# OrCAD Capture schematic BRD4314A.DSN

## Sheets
1 05: Debugger: size A3; title: BGM220P Explorer Kit; rev: A01; company: Silicon Labs; note: BRD4314A; note: MAH; note: RGU
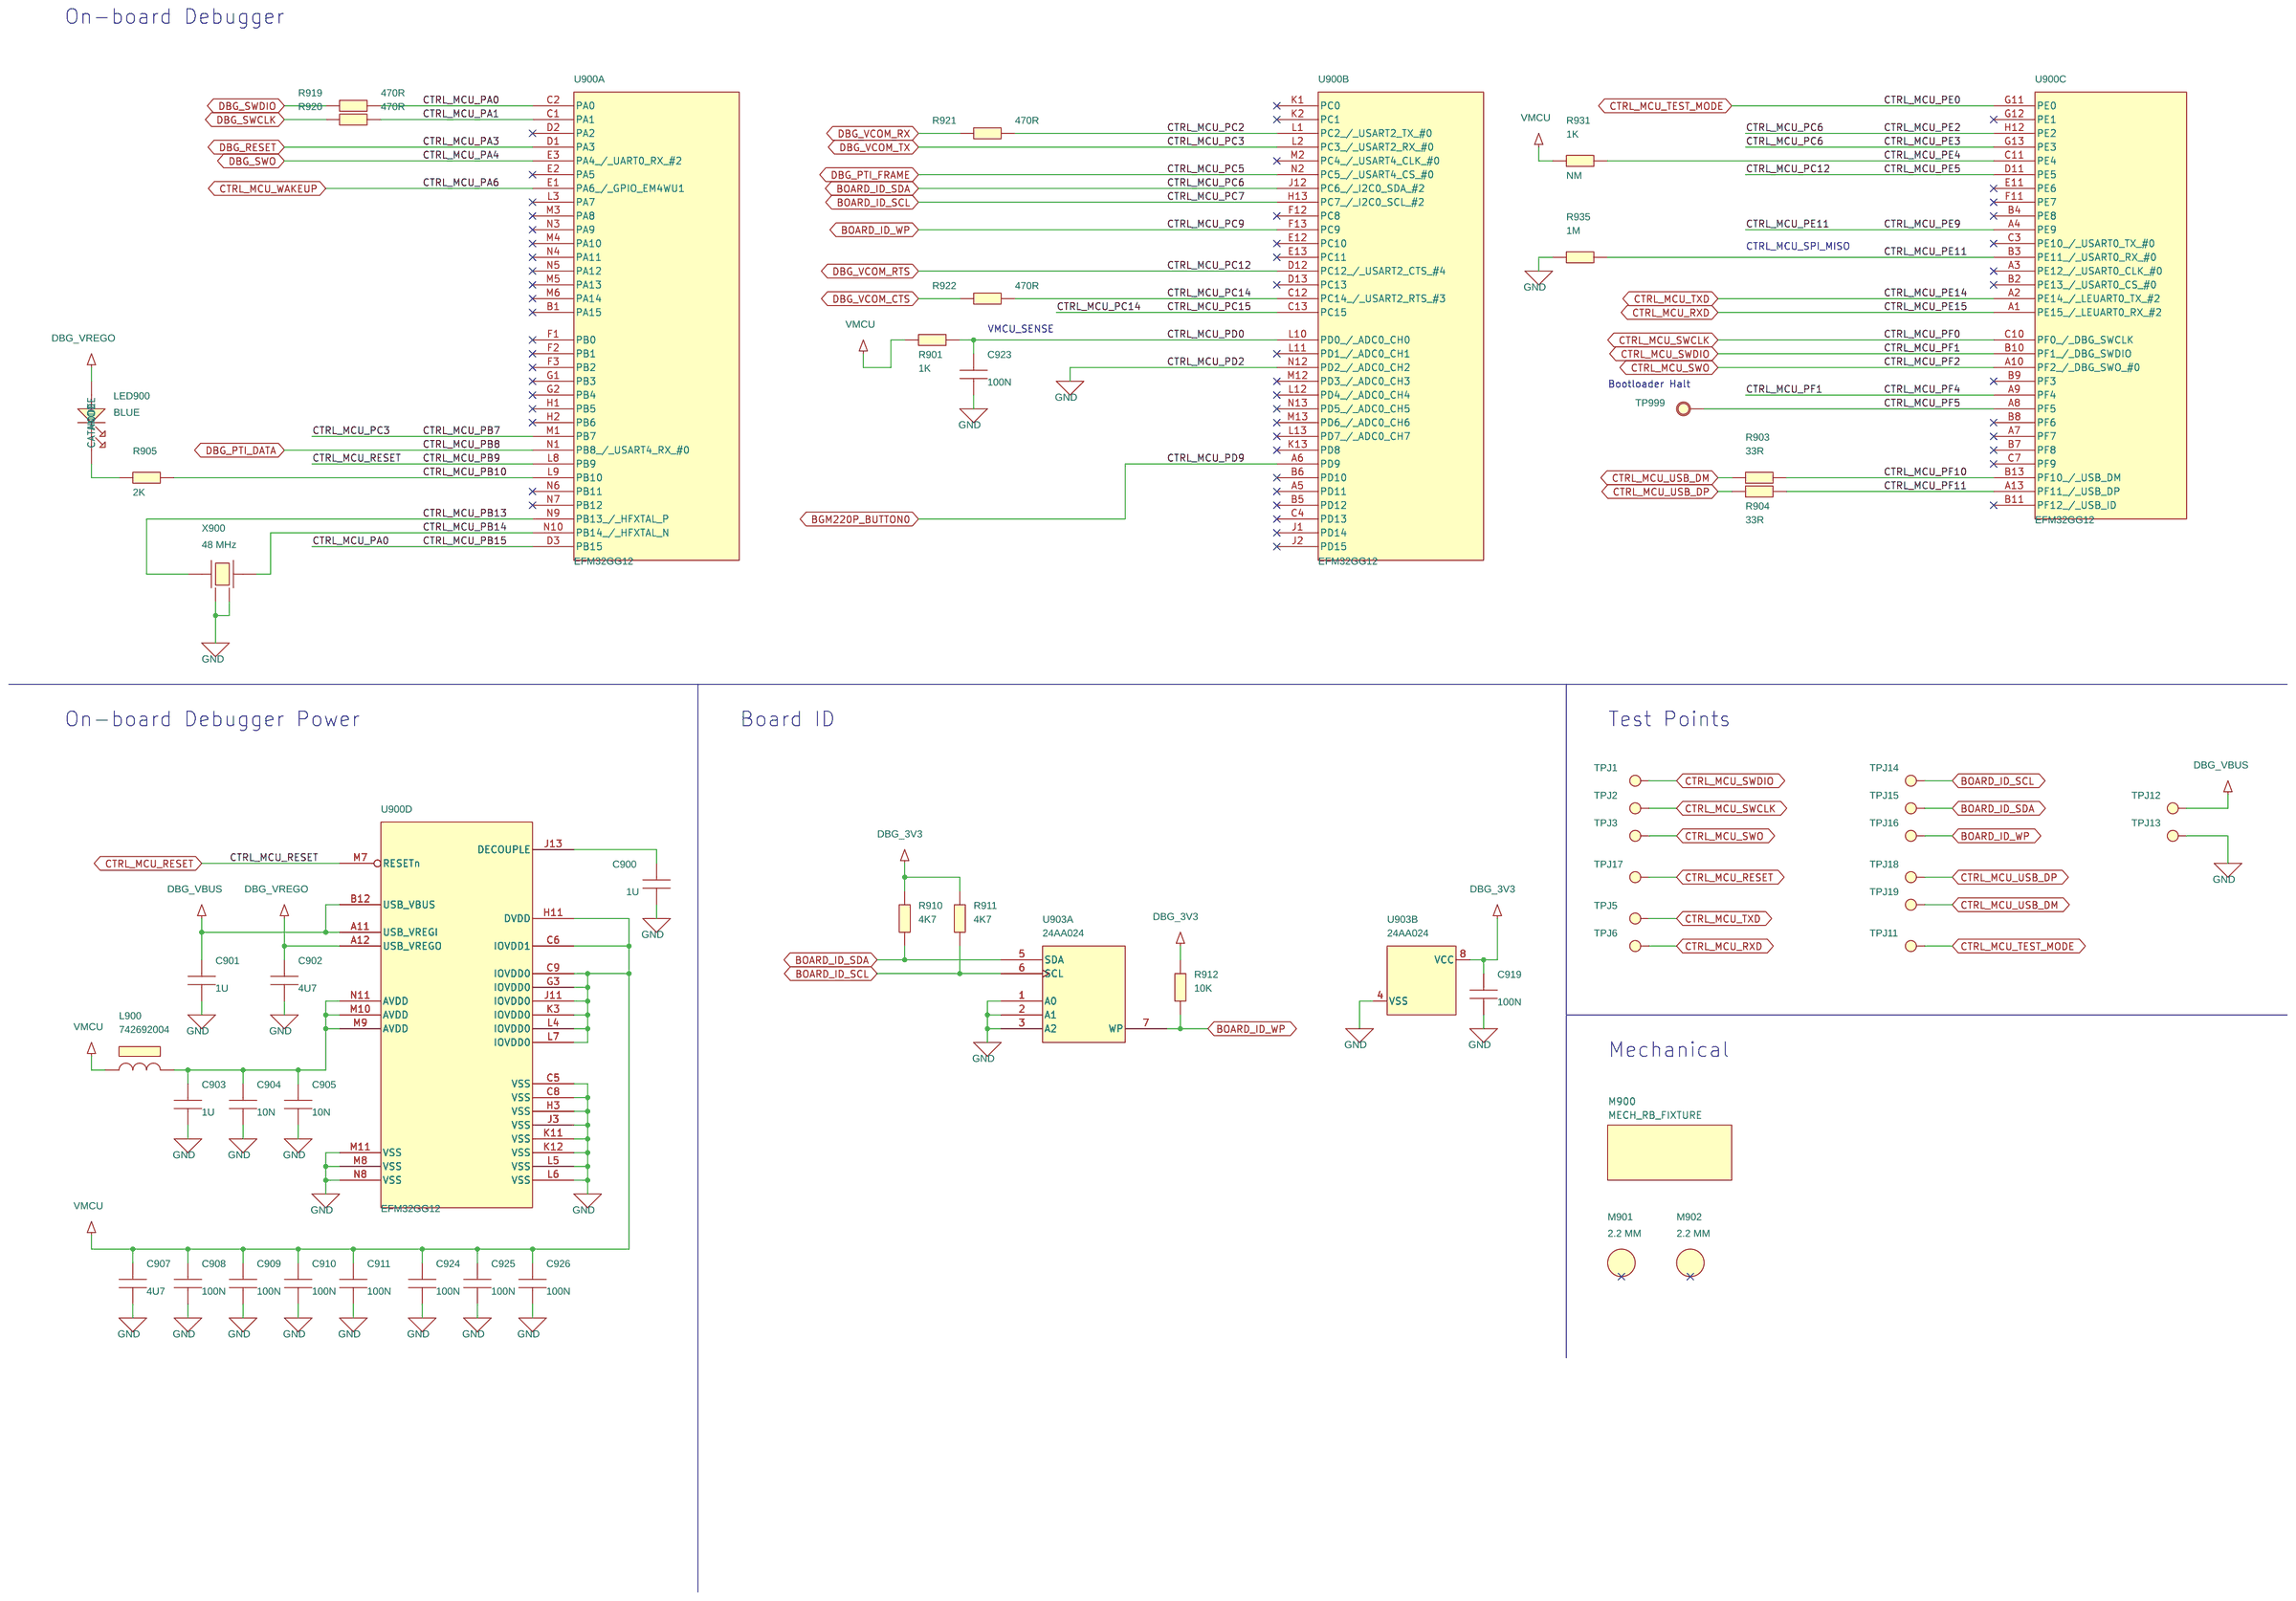
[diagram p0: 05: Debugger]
2 02: BGM220P: size A3
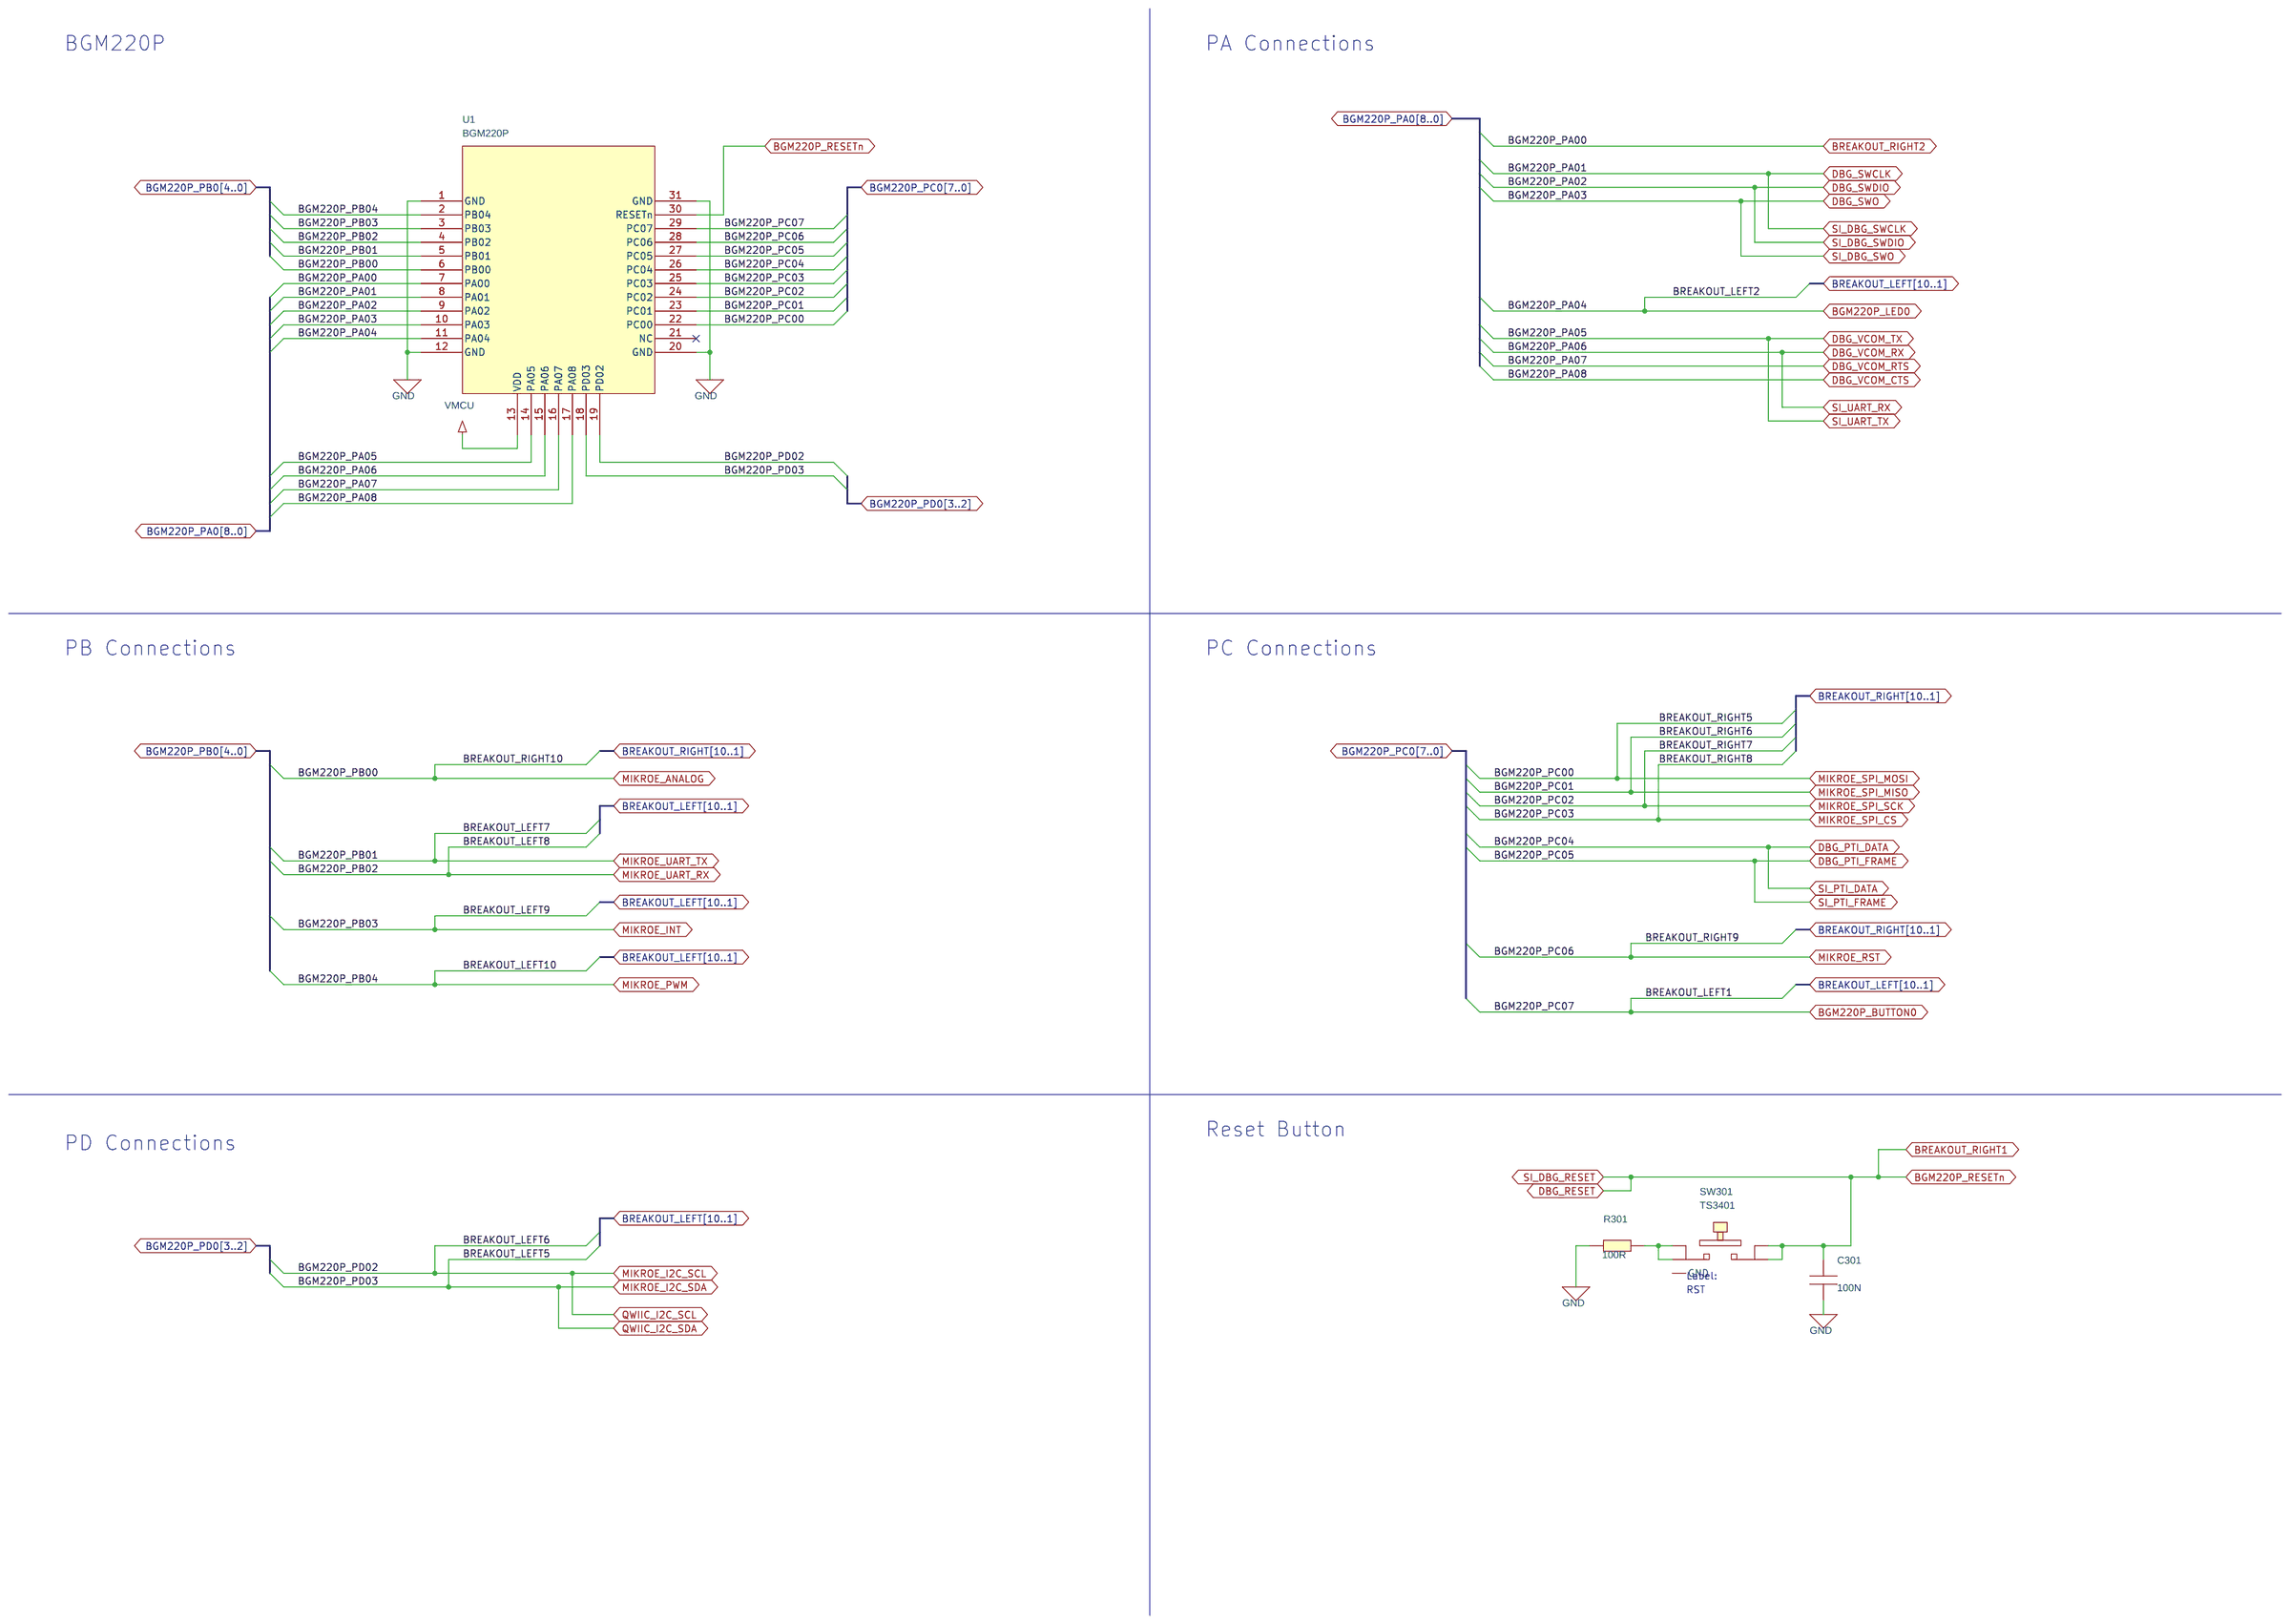
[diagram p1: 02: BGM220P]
3 04: Board Power: size A3
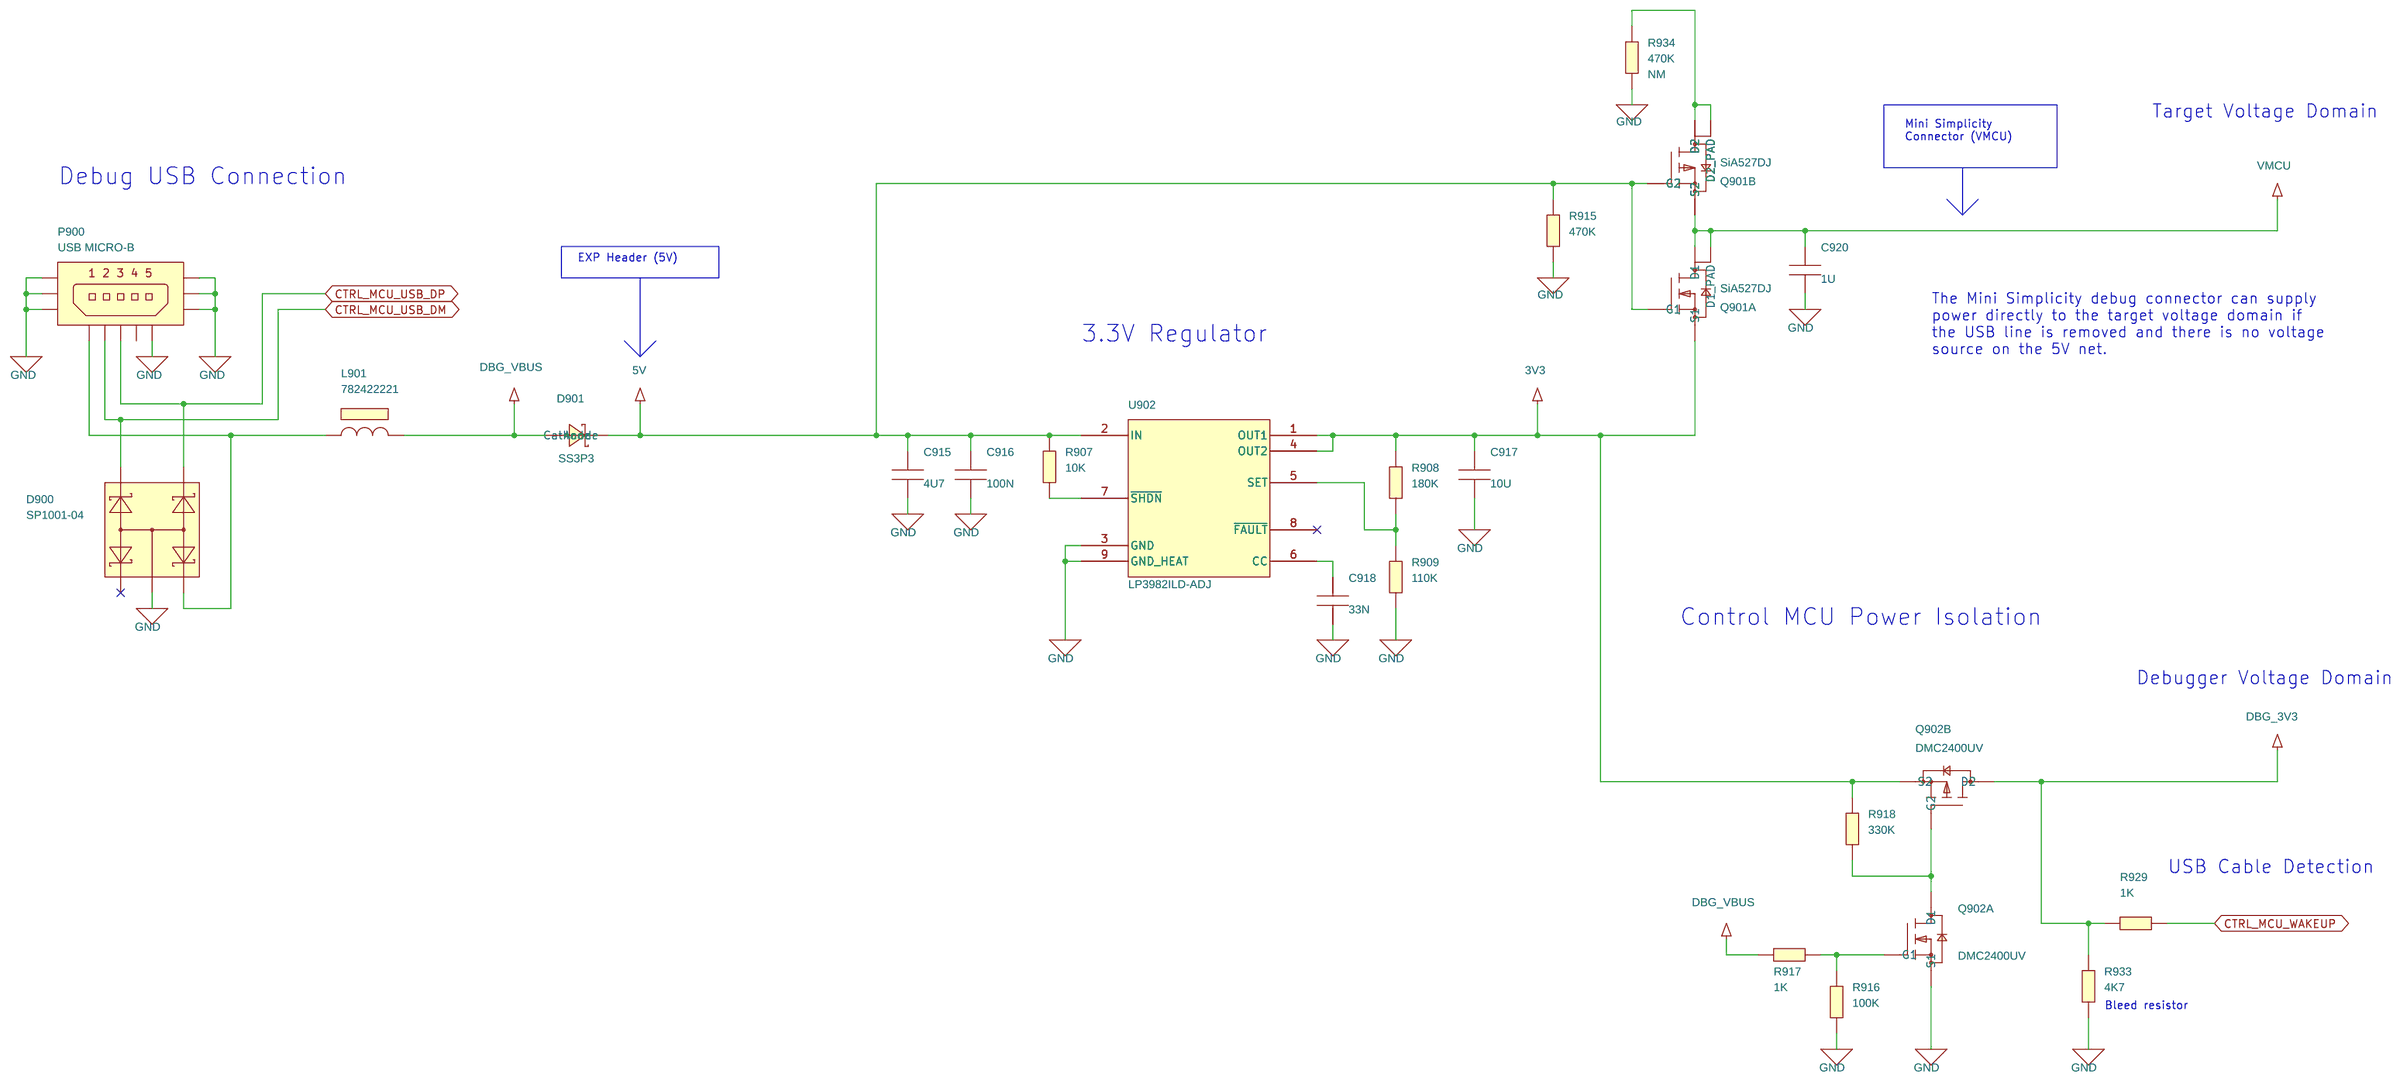
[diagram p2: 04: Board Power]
4 01: Title Page
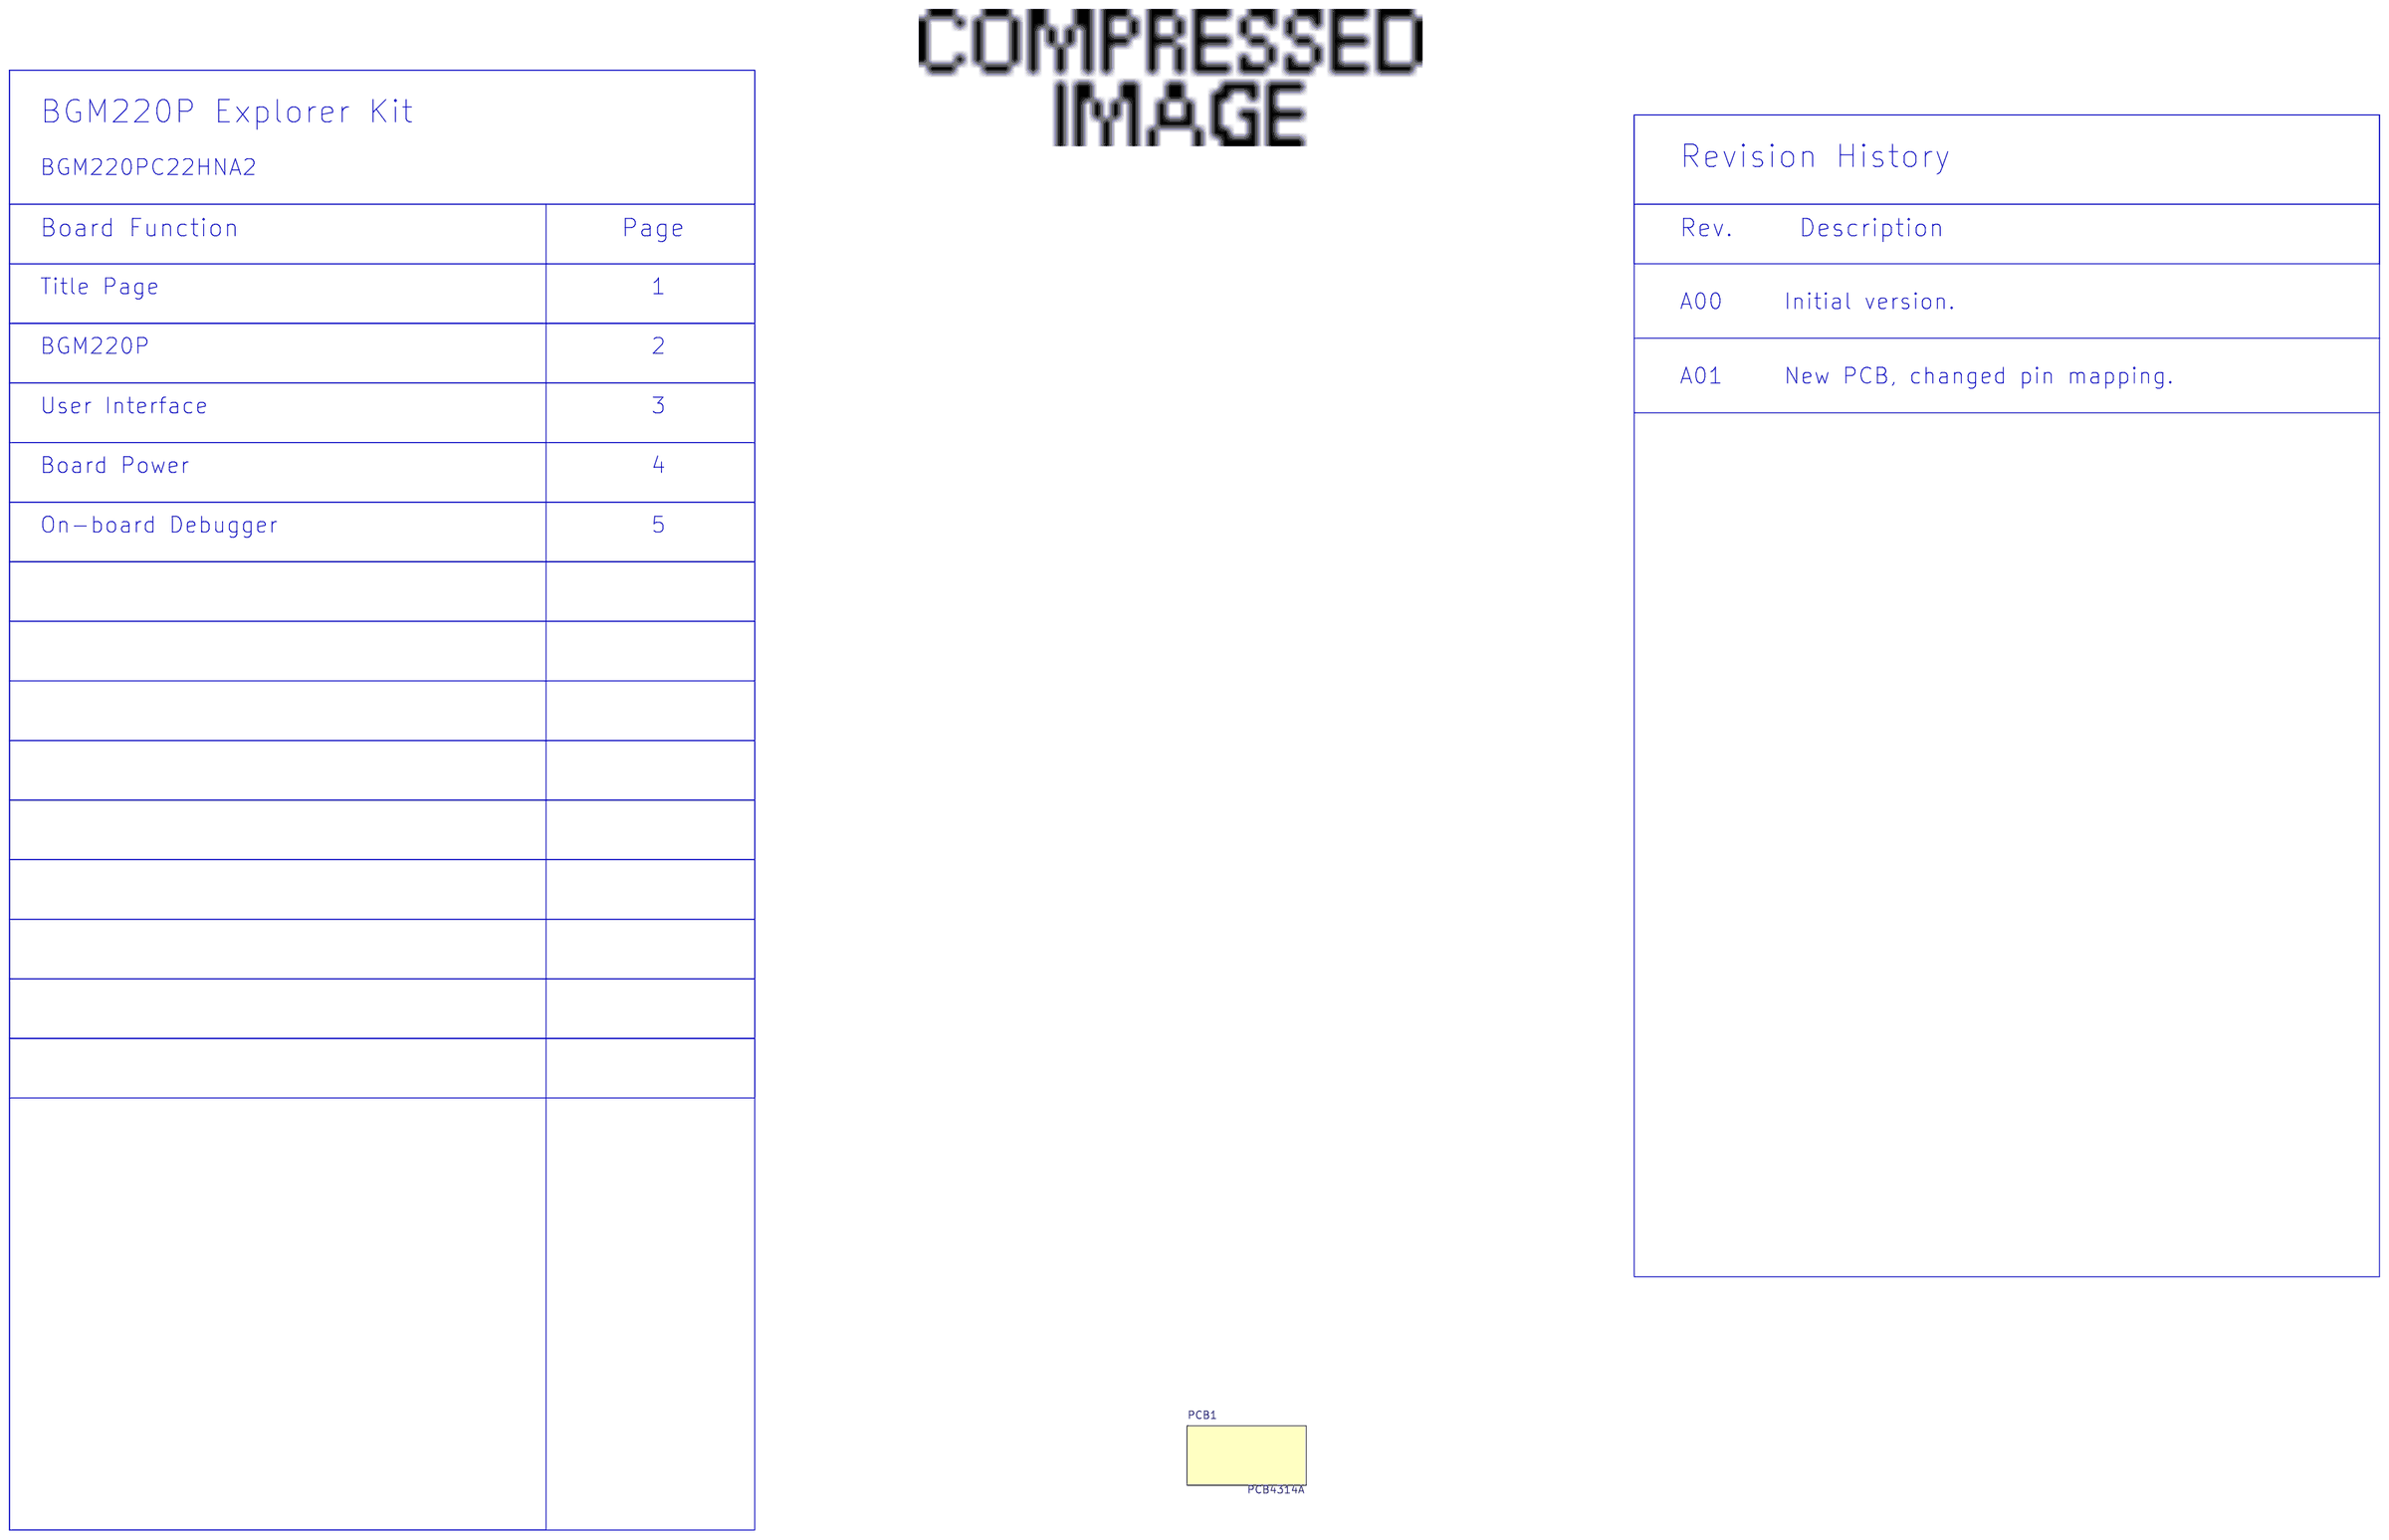
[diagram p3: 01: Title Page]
5 03: User Interface: size A3
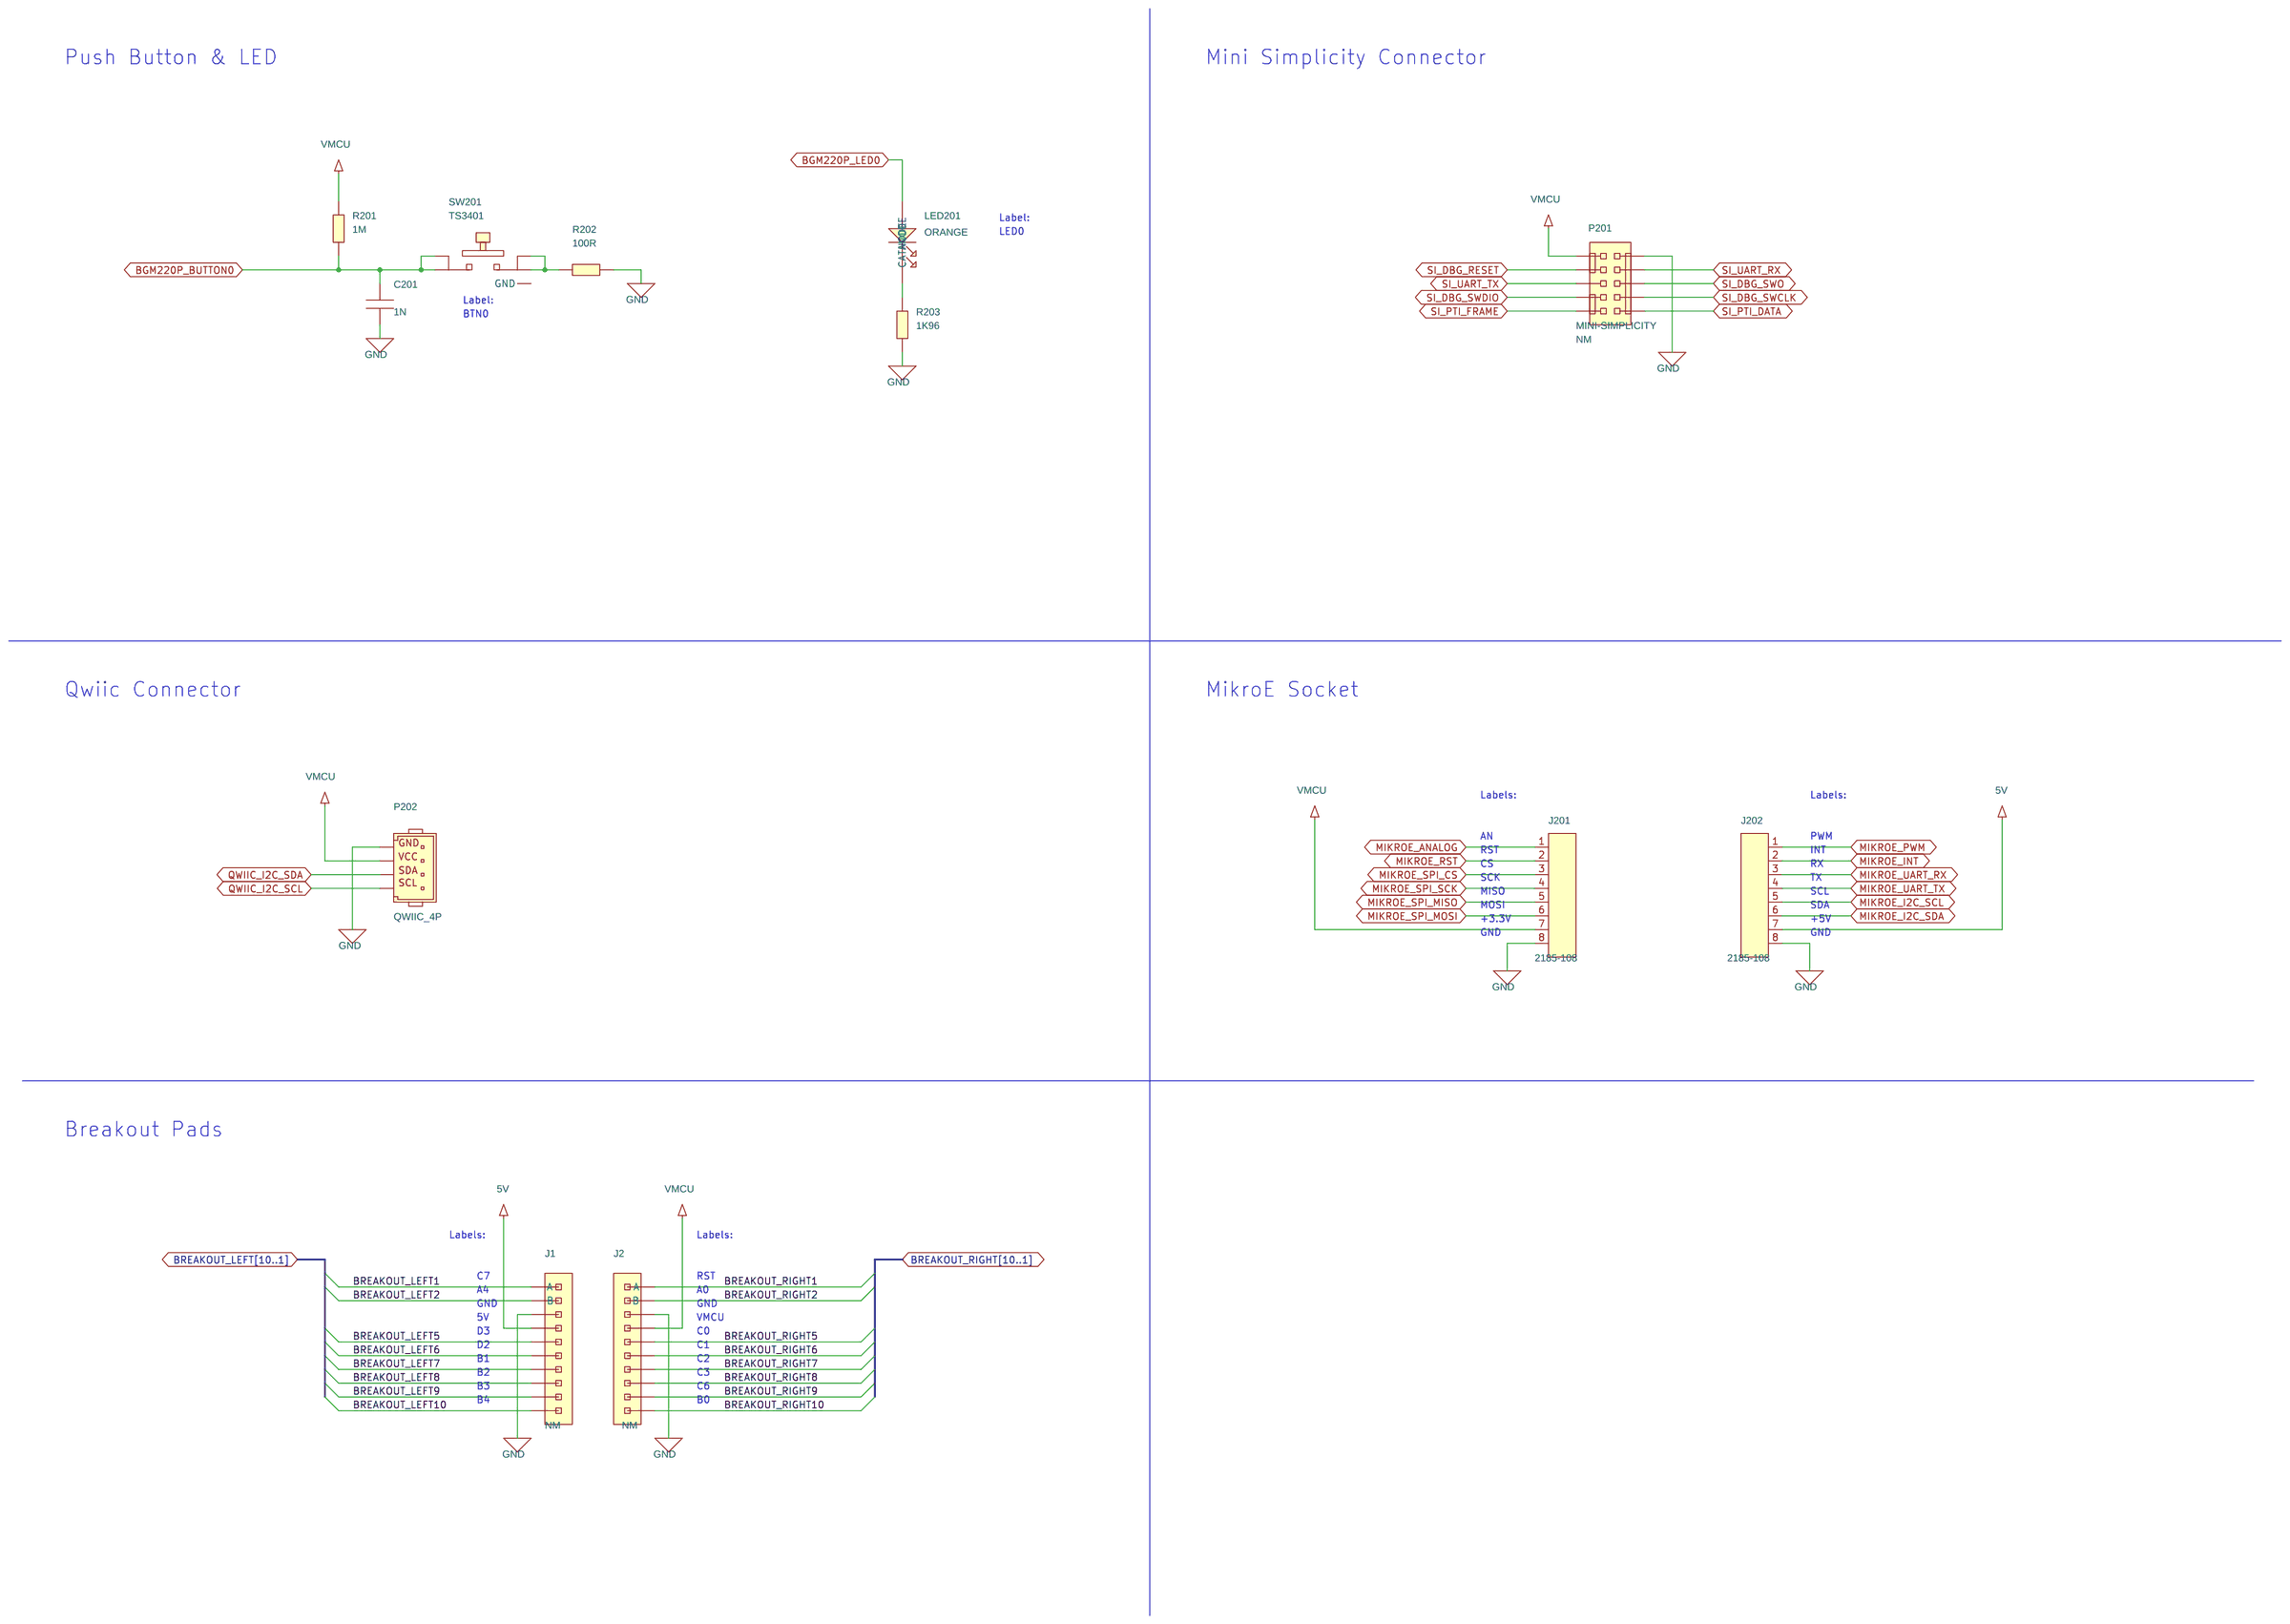
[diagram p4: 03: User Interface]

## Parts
sheet 01: Title Page
PCB1  PCB4314A  [N/A]
sheet 02: BGM220P
C301  100N  [C0201_L]
R301  100R  [R0201_L]
SW301  TS3401  [SWITCH_CK_PTS810]
U1  BGM220P  [MODULE_BGM220P]
sheet 03: User Interface
C201  1N  [C0201_L]
J1  1X10 2.54MM  [HEADER_10X1_2.54MM_TH]
J2  1X10 2.54MM  [HEADER_10X1_2.54MM_TH]
J201  2185-108  [WCON_2185-108M-1X8]
J202  2185-108  [WCON_2185-108M-1X8]
LED201  ORANGE  [LED0402_L]
P201  MINI-SIMPLICITY  [FTSH_105_01_L_DV_K]
P202  QWIIC_4P  [WCON_WF1001A-WM04E-4]
R201  1M  [R0201_L]
R202  100R  [R0201_L]
R203  1K96  [R0201_L]
SW201  TS3401  [SWITCH_CK_PTS810]
sheet 04: Board Power
C915  4U7  [C0603_L]
C916  100N  [C0201_L]
C917  10U  [C0603_L]
C918  33N  [C0201_L]
C920  1U  [C0402_L]
D900  SP1001-04  [SOT553_L]
D901  SS3P3  [DO-220AA]
L901  782422221  [COIL_0402]
P900  USB MICRO-B  [AMP_FCI_10118194]
Q901  SiA527DJ  [POWERPAK_SC70-6_L]  (sections A,B)
Q902  DMC2400UV  [SOT563_L]  (sections A,B)
R907  10K  [R0201_L]
R908  180K  [R0201_L]
R909  110K  [R0201_L]
R915  470K  [R0201_L]
R916  100K  [R0201_L]
R917  1K  [R0201_L]
R918  330K  [R0201_L]
R929  1K  [R0201_L]
R933  4K7  [R0201_L]
R934  470K  [R0201_L]
U902  LP3982ILD-ADJ  [LLP8]
sheet 05: Debugger
C900  1U  [C0402_L]
C901  1U  [C0402_L]
C902  4U7  [C0603_L]
C903  1U  [C0402_L]
C904  10N  [C0201_L]
C905  10N  [C0201_L]
C907  4U7  [C0603_L]
C908  100N  [C0201_L]
C909  100N  [C0201_L]
C910  100N  [C0201_L]
C911  100N  [C0201_L]
C919  100N  [C0201_L]
C923  100N  [C0201_L]
C924  100N  [C0201_L]
C925  100N  [C0201_L]
C926  100N  [C0201_L]
L900  742692004  [COIL_0201_L]
LED900  BLUE  [LED0402_L]
M900  MECH_RB_FIXTURE  [MECH_RB_FIXTURE_SL]
M901  2.2 MM  [HOLE_2.2_NPL]
M902  2.2 MM  [HOLE_2.2_NPL]
R901  1K  [R0201_L]
R903  33R  [R0402_L]
R904  33R  [R0402_L]
R905  2K  [R0201_L]
R910  4K7  [R0201_L]
R911  4K7  [R0201_L]
R912  10K  [R0201_L]
R919  470R  [R0201_L]
R920  470R  [R0201_L]
R921  470R  [R0201_L]
R922  470R  [R0201_L]
R931  1K  [R0201_L]
R935  1M  [R0201_L]
TP999  PROTO_TH  [PROTO_TH]
TPJ1  TPJ_SMD  [TP_1.0_SMD]
TPJ2  TPJ_SMD  [TP_1.0_SMD]
TPJ3  TPJ_SMD  [TP_1.0_SMD]
TPJ5  TPJ_SMD  [TP_1.0_SMD]
TPJ6  TPJ_SMD  [TP_1.0_SMD]
TPJ11  TPJ_SMD  [TP_1.0_SMD]
TPJ12  TPJ_SMD  [TP_1.0_SMD]
TPJ13  TPJ_SMD  [TP_1.0_SMD]
TPJ14  TPJ_SMD  [TP_1.0_SMD]
TPJ15  TPJ_SMD  [TP_1.0_SMD]
TPJ16  TPJ_SMD  [TP_1.0_SMD]
TPJ17  TPJ_SMD  [TP_1.0_SMD]
TPJ18  TPJ_SMD  [TP_1.0_SMD]
TPJ19  TPJ_SMD  [TP_1.0_SMD]
U900  EFM32GG12  [BGA120_M050_7.0X7.0_EFM32GGR]  (sections A,B,C,D)
U903  24AA024  [TDFN8_M050_2.0x3.0_EP]  (sections A,B)
X900  48 MHz  [X_SSS_DSX211SH_2.05X1.65-4]

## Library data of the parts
PCB1 = PCB: Mfg #: PCB4314A Rev. A01; Price_1K: 0.35
C301 C908-C911 C916 C919 C923-C926 = C0201: Price_1K: 0.0016; Rating: 10V; Technology: X5R; Tolerance: 10%
R201-R203 R301 R901 R905 R907-R912 R915-R922 R929 R933 R935 = R0201: Tolerance: 1%
SW201 SW301 = SWITCH_CK_PTS810: Mfg: KLS; Mfg #: L-KLS7-TS3401-2.5-160-R; Price_1K: 0.05
U1 = xGM220P: Mfg #: BGM220PC22HNA2
C201 = C0201: Price_1K: 0.004; Rating: 50V; Technology: X7R; Tolerance: 10%
J1 J2 = HEADER_1X10_2.54MM_TH: Not Mounted: NM
J201 J202 = 2185-108
LED201 = LED_0402: Mfg: Vishay Semiconductor; Mfg #: VLMY1500-GS08; Price_1K: 0.1
P201 = FTSH_105_01_L_DV_K: Mfg: WCON; Mfg #: 3132-10MS3BK00R3; Not Mounted: NM; Price_1K: 0.55
P202 = GROVE_4P_SMD_VERT_3: Mfg: WCON; Mfg #: WF1001A-WM04ER1; Price_1K: 0.12
C902 C907 C915 = C0603: Price_1K: 0.025; Rating: 16V; Technology: X5R; Tolerance: 20%
C917 = C0603: Price_1K: 0.06; Rating: 10V; Technology: X5R; Tolerance: 20%
C918 = C0201: Price_1K: 0.01; Rating: 16V; Technology: X5R; Tolerance: 10%
C900 C901 C903 C920 = C0402: Price_1K: 0.002; Rating: 10V; Technology: X5R; Tolerance: 10%
D900 = SP1001-04: Price_1K: 0.187
D901 = SS3P3
L901 = WE-CBA: Mfg: Würth Elektronik
P900 = KLS_L-KLS1-238-0-0-0
Q901 = SiA527DJ
Q902 = DMC2400UV: Price_1K: 0.0319
R931 R934 = R0201: Not Mounted: NM; Tolerance: 1%
U902 = LP3982ILD-ADJ: CONTEC Footprint: LLP8_M050_W2.5X3.0_HEAT; Price_1K: 0.178
C904 C905 = C0201: Price_1K: 0.004; Rating: 10V; Technology: X7R; Tolerance: 10%
L900 = WE-TMSB
LED900 = LED_0402: Mfg: Lucky Light; Mfg #: S160BC-B4-1BJ; Price_1K: 0.037
M900 = MECH_RB_FIXTURE
M901 M902 = HOLE_2.2_NPL
R903 R904 = R0402: Tolerance: 1%
TP999 = PROTO_TH: CONTEC Footprint: TP_1.0_TH
TPJ1-TPJ3 TPJ5 TPJ6 TPJ11-TPJ19 = TPJ_SMD: Not Mounted: NM
U900 = EFM32GG12B410F1024GL120-DBG
U903 = 24AA024: ComponentGroup: DBGEEPROM; Mfg #: 24AA024T-I/MNY; Price_1K: 0.227
X900 = DSX211SH: Mfg: Tai-Saw; Mfg #: TZ3139C; Price_1K: 0.063

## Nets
3V3: C917.1 Q901.1(S1) Q902.4(S2) R908.2 R918.2 U902.1(OUT1) U902.4(OUT2)
5V: C915.1 C916.1 D901.1(Cathode) J1.4 J202.7 Q901.2(G1) Q901.5(G2) R907.2 R915.2 U902.2(IN)
GND: C201.2 C301.2 C900.2 C901.2 C902.2 C903.2 C904.2 C905.2 C907.2 C908.2 C909.2 C910.2 C911.2 C915.2 C916.2 C917.2 C918.2 C919.2 C920.2 C923.2 C924.2 C925.2 C926.2 D900.2 J1.3 J2.3 J201.8 J202.8 P201.2 P202.1 P900.5 P900.6 P900.7 P900.8 P900.9 P900.10 P900.11 Q902.1(S1) R202.2 R203.1 R301.1 R909.1 R915.1 R916.1 R933.2 R934.1 R935.2 SW201.5(GND) SW301.5(GND) TPJ13.1(TP) U1.1(GND) U1.12(GND) U1.20(GND) U1.31(GND) U900.C5(VSS) U900.C8(VSS) U900.H3(VSS) U900.J3(VSS) U900.K11(VSS) U900.K12(VSS) U900.L5(VSS) U900.L6(VSS) U900.M8(VSS) U900.M11(VSS) U900.N8(VSS) U900.N12(PD2_/_ADC0_CH2) U902.3(GND) U902.9(GND_HEAT) U903.1(A0) U903.2(A1) U903.3(A2) U903.4(VSS) X900.2 X900.4
BGM220P_BUTTON0: C201.1 J1.1(A) R201.2 SW201.1 SW201.2 U1.29(PC07) U900.A6(PD9)
BGM220P_LED0: J1.2(B) LED201.2(ANODE) U1.11(PA04)
BGM220P_PA00: J2.2(B) U1.7(PA00)
BGM220P_PA01: P201.8 R920.2 U1.8(PA01)
BGM220P_PA02: P201.7 R919.2 U1.9(PA02)
BGM220P_PA03: P201.6 U1.10(PA03) U900.E3(PA4_/_UART0_RX_#2)
BGM220P_PA05: P201.5 U1.14(PA05) U900.L2(PC3_/_USART2_RX_#0) U900.M1(PB7)
BGM220P_PA06: P201.4 R921.2 U1.15(PA06)
BGM220P_PA07: U1.16(PA07) U900.D11(PE5) U900.D12(PC12_/_USART2_CTS_#4)
BGM220P_PA08: R922.2 U1.17(PA08)
BGM220P_PB00: J2.10 J201.1 U1.6(PB00)
BGM220P_PB01: J1.7 J202.4 U1.5(PB01)
BGM220P_PB02: J1.8 J202.3 U1.4(PB02)
BGM220P_PB03: J1.9 J202.2 U1.3(PB03)
BGM220P_PB04: J1.10 J202.1 U1.2(PB04)
BGM220P_PC00: J2.5 J201.6 U1.22(PC00)
BGM220P_PC01: J2.6 J201.5 U1.23(PC01)
BGM220P_PC02: J2.7 J201.4 U1.24(PC02)
BGM220P_PC03: J2.8 J201.3 U1.25(PC03)
BGM220P_PC04: P201.10 U1.26(PC04) U900.N1(PB8_/_USART4_RX_#0)
BGM220P_PC05: P201.9 U1.27(PC05) U900.N2(PC5_/_USART4_CS_#0)
BGM220P_PC06: J2.9 J201.2 U1.28(PC06)
BGM220P_PD02: J1.6 J202.5 P202.4 U1.19(PD02)
BGM220P_PD03: J1.5 J202.6 P202.3 U1.18(PD03)
BGM220P_RESETn: C301.1 J2.1(A) P201.3 SW301.1 SW301.2 U1.30(RESETn) U900.D1(PA3)
BOARD_ID_SCL: R911.1 TPJ14.1(TP) U900.H13(PC7_/_I2C0_SCL_#2) U903.6(SCL)
BOARD_ID_SDA: R910.1 TPJ15.1(TP) U900.G13(PE3) U900.H12(PE2) U900.J12(PC6_/_I2C0_SDA_#2) U903.5(SDA)
BOARD_ID_WP: R912.1 TPJ16.1(TP) U900.F13(PC9) U903.7(WP)
CTRL_MCU_PA0: R919.1 U900.C2(PA0) U900.D3(PB15)
CTRL_MCU_PA1: R920.1 U900.C1(PA1)
CTRL_MCU_PB10: R905.1 U900.L9(PB10)
CTRL_MCU_PB13: U900.N9(PB13_/_HFXTAL_P) X900.3
CTRL_MCU_PB14: U900.N10(PB14_/_HFXTAL_N) X900.1
CTRL_MCU_PC2: R921.1 U900.L1(PC2_/_USART2_TX_#0)
CTRL_MCU_PC14: R922.1 U900.C12(PC14_/_USART2_RTS_#3) U900.C13(PC15)
CTRL_MCU_PD0: C923.1 R901.1 U900.L10(PD0_/_ADC0_CH0)
CTRL_MCU_PE4: R931.1 U900.C11(PE4)
CTRL_MCU_PE11: R935.1 U900.A4(PE9) U900.B3(PE11_/_USART0_RX_#0)
CTRL_MCU_PF5: TP999.1(VIA) U900.A8(PF5)
CTRL_MCU_PF10: R903.2 U900.B13(PF10_/_USB_DM)
CTRL_MCU_PF11: R904.2 U900.A13(PF11_/_USB_DP)
CTRL_MCU_RESET: TPJ17.1(TP) U900.L8(PB9) U900.M7(RESETn)
CTRL_MCU_RXD: TPJ6.1(TP) U900.A1(PE15_/_LEUART0_RX_#2)
CTRL_MCU_SWCLK: TPJ2.1(TP) U900.C10(PF0_/_DBG_SWCLK)
CTRL_MCU_SWDIO: TPJ1.1(TP) U900.A9(PF4) U900.B10(PF1_/_DBG_SWDIO)
CTRL_MCU_SWO: TPJ3.1(TP) U900.A10(PF2_/_DBG_SWO_#0)
CTRL_MCU_TEST_MODE: TPJ11.1(TP) U900.G11(PE0)
CTRL_MCU_TXD: TPJ5.1(TP) U900.A2(PE14_/_LEUART0_TX_#2)
CTRL_MCU_USB_DM: D900.5 P900.2 R903.1 TPJ19.1(TP)
CTRL_MCU_USB_DP: D900.4 P900.3 R904.1 TPJ18.1(TP)
CTRL_MCU_WAKEUP: R929.1 U900.E1(PA6_/_GPIO_EM4WU1)
DBG_3V3: C919.1 Q902.3(D2) R910.2 R911.2 R912.2 R929.2 R933.1 U903.8(VCC)
DBG_VBUS: C901.1 D901.2(Anode) L901.2 R917.2 TPJ12.1(TP) U900.A11(USB_VREGI) U900.B12(USB_VBUS)
DBG_VREGO: C902.1 LED900.2(ANODE) U900.A12(USB_VREGO)
VMCU: C907.1 C908.1 C909.1 C910.1 C911.1 C920.1 C924.1 C925.1 C926.1 J2.4 J201.7 L900.1 P201.1 P202.2 Q901.4(S2) Q901.6(D1) Q901.7(D1_PAD) R201.1 R901.2 R931.2 U1.13(VDD) U900.C6(IOVDD1) U900.C9(IOVDD0) U900.G3(IOVDD0) U900.H11(DVDD) U900.J11(IOVDD0) U900.K3(IOVDD0) U900.L4(IOVDD0) U900.L7(IOVDD0)
N16782098: LED201.1(CATHODE) R203.2
N16786878: R202.1 SW201.3 SW201.4
N16788367: D900.3 L901.1 P900.1
N16788394: R908.1 R909.2 U902.5(SET)
N16788408: R907.1 U902.7(~{SHDN})
N16788424: C918.1 U902.6(CC)
N16791923: LED900.1(CATHODE) R905.2
N16793325: C900.1 U900.J13(DECOUPLE)
N16793347: C903.1 C904.1 C905.1 L900.2 U900.M9(AVDD) U900.M10(AVDD) U900.N11(AVDD)
N16822845: R301.2 SW301.3 SW301.4
N16862939: Q901.3(D2) Q901.8(D2_PAD) R934.2
N16974649: Q902.2(G1) R916.2 R917.1
N16974657: Q902.5(G2) Q902.6(D1) R918.1

Not connected (* = marked no-connect by the designer): D900 1*; M901 0*; M902 0*; P900 4; U1 21(NC)*; U900 A3(PE12_/_USART0_CLK_#0)* A5(PD11)* A7(PF7)* B1(PA15)* B2(PE13_/_USART0_CS_#0)* B4(PE8)* B5(PD12)* B6(PD10)* B7(PF8)* B8(PF6)* B9(PF3)* B11(PF12_/_USB_ID)* C3(PE10_/_USART0_TX_#0)* C4(PD13)* C7(PF9)* D2(PA2)* D13(PC13)* E2(PA5)* E11(PE6)* E12(PC10)* E13(PC11)* F1(PB0)* F2(PB1)* F3(PB2)* F11(PE7)* F12(PC8)* G1(PB3)* G2(PB4)* G12(PE1)* H1(PB5)* H2(PB6)* J1(PD14)* J2(PD15)* K1(PC0)* K2(PC1)* K13(PD8)* L3(PA7)* L11(PD1_/_ADC0_CH1)* L12(PD4_/_ADC0_CH4)* L13(PD7_/_ADC0_CH7)* M2(PC4_/_USART4_CLK_#0)* M3(PA8)* M4(PA10)* M5(PA13)* M6(PA14)* M12(PD3_/_ADC0_CH3)* M13(PD6_/_ADC0_CH6)* N3(PA9)* N4(PA11)* N5(PA12)* N6(PB11)* N7(PB12)* N13(PD5_/_ADC0_CH5)*; U902 8(~{FAULT})*

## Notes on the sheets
sheet 1
- On-board Debugger
- CTRL_MCU_SPI_MISO
- VMCU_SENSE
- Bootloader Halt
- On-board Debugger Power
- Board ID
- Test Points
- Mechanical
sheet 2
- BGM220P
- PA Connections
- PB Connections
- PC Connections
- Reset Button
- PD Connections
- Label:
- RST
sheet 3
- Target Voltage Domain
- Mini Simplicity
  Connector (VMCU)
- Debug USB Connection
- EXP Header (5V)
- The Mini Simplicity debug connector can supply
  power directly to the target voltage domain if
  the USB line is removed and there is no voltage
  source on the 5V net.
- 3.3V Regulator
- Control MCU Power Isolation
- Debugger Voltage Domain
- USB Cable Detection
- Bleed resistor
sheet 4
- BGM220P Explorer Kit
- Revision History
- BGM220PC22HNA2
- Board Function
- Page
- Rev.
- Description
- Title Page
- 1
- A00
- Initial version.
- BGM220P
- 2
- A01
- New PCB, changed pin mapping.
- User Interface
- 3
- Board Power
- 4
- On-board Debugger
- 5
sheet 5
- Push Button & LED
- Mini Simplicity Connector
- Label:
- LED0
- Label:
- BTN0
- Qwiic Connector
- MikroE Socket
- Labels:
- Labels:
- AN
- PWM
- RST
- INT
- CS
- SCK
- RX
- TX
- MISO
- SCL
- MOSI
- SDA
- +3.3V
- +5V
- GND
- GND
- Breakout Pads
- Labels:
- Labels:
- C7
- RST
- A4
- A0
- GND
- GND
- 5V
- D3
- C0
- VMCU
- D2
- C1
- B1
- C2
- B2
- C3
- B3
- C6
- B4
- B0
